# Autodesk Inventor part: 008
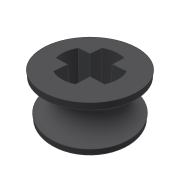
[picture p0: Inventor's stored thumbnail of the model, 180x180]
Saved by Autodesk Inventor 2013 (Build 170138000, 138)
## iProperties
Created: 2012-02
Part Number: 008
Material: Generic
Document SubType Name: Modeling
Designer: perblt
Density: 1 g/cm^3
Author: perblt
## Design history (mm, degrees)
node "42115731"
node "4211573"
node "Base1"
